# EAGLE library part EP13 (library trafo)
TRANSFORMER 1 primary winding, 2 secondary windings BLOCK
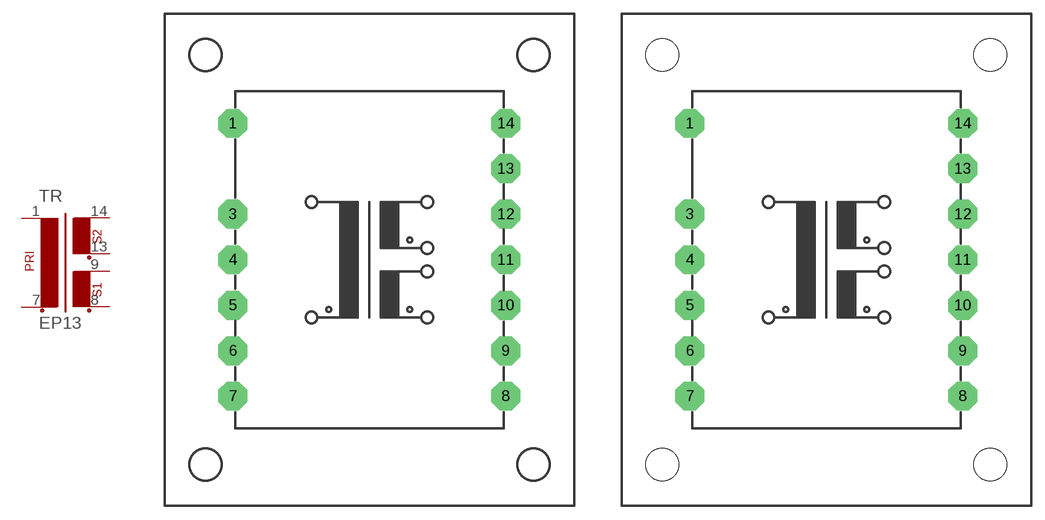
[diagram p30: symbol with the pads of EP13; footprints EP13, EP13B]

Designator prefix TR

## EP13  [EP13]
1  1  pas
7  2  pas
8  3  pas
9  4  pas
13  5  pas
14  6  pas

## EP13MH  [EP13B]
Pads as for EP13

## Footprint EP13 (pad centres in mm)
TRANSFORMER 1 primary winding, 2 secondary windings
drill 1.118 pad 3.175 octagon: 1 -14.986,14.986; 3 -14.986,5.004; 4 -14.986,0; 5 -14.986,-5.004; 6 -14.986,-10.008; 7 -14.986,-14.986; 8 14.986,-14.986; 9 14.986,-10.008; 10 14.986,-5.004; 11 14.986,0; 12 14.986,5.004; 13 14.986,10.008; 14 14.986,14.986

## Footprint EP13B (pad centres in mm)
TRANSFORMER 1 primary winding, 2 secondary windings, mounting holes
drill 1.118 pad 3.175 octagon: 1 -14.986,14.986; 3 -14.986,5.004; 4 -14.986,0; 5 -14.986,-5.004; 6 -14.986,-10.008; 7 -14.986,-14.986; 8 14.986,-14.986; 9 14.986,-10.008; 10 14.986,-5.004; 11 14.986,0; 12 14.986,5.004; 13 14.986,10.008; 14 14.986,14.986
hole 3.607 at -18.009,22.504
hole 3.607 at -18.009,-22.504
hole 3.607 at 18.009,22.504
hole 3.607 at 18.009,-22.504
